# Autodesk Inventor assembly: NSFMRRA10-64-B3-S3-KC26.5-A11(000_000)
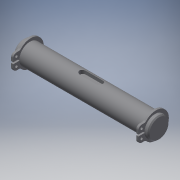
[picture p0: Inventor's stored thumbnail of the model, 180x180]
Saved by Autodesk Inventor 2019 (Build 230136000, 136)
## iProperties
Category: PARTsolutions
Company: MISUMI
Created: 2022-11
Part Number: NSFMRRA10-64-B3-S3-KC26.5-A11(000_000)
Catalog Web Link: www.cadenas.de
Description: NSFMRR, SFMRR, PSFMRR, SSFMRR, NSFHRR, SFHRR, PSFHRR, SSFHRR, NSFRR, SFRR, PSFRR, SSFRR, NSFMRRA, SFMRRA, PSFMRRA, SSFMRRA, NSFHRRA, SFHRRA, PSFHRRA, SSFHRRA, N
Vendor: MISUMI
Document SubType Name: Assembly
Designer: psAdmin
Manufacturer: MISUMI
Mass: 5.06966 g
Surface Area: 26.1875 cm^2
Volume: 5.06966 cm^3
Density: 1 g/cm^3
Title: NSFMRRA10-64-B3-S3-KC26.5-A11
Author: Cadenas PARTsolutions
Comments: Rotary Shafts - Retaining Ring Grooves on Both Ends - Standard
PSOL_IDENT_0: {$CADENAS_DATA/23d-libs/misumi/metric/11_rotary_shafts/psfrra_asmtab.prj},820 {VTYP=3D},{STYP=ASSTAB
PSOL_IDENT_1: },{NB=NSFMRRA10-64-B3-S3-KC26.5-A11(000_000)},{LINA=NSFMRRA10-64-B3-S3-KC26.5-A11},{NN=NSFMRR, SFMRR
PSOL_IDENT_2: , PSFMRR, SSFMRR, NSFHRR, SFHRR, PSFHRR, SSFHRR, NSFRR, SFRR, PSFRR, SSFRR, NSFMRRA, SFMRRA, PSFMRRA
PSOL_IDENT_3: , SSFMRRA, NSFHRRA, SFHRRA, PSFHRRA, SSFHRRA, NSFRRA, SFRRA, PSFRRA, SSFRRA, HFRRA, PHFRRA, PSFRR PS
PSOL_IDENT_4: FRRA, PSFHRR, PSFHRRA, SSFRR, SSFRRA, SSFHRR, SSFHRRA, PPSFRR, PPSFRRA, PPSFHRR, PPSFHRRA, SSSFRR, S
PSOL_IDENT_5: SSFRRA, SSSFHRR, SSSFHRRA_shaft},{DATE=21.04.2022 07:40:19},{GEOMDATE=27.07.2021 08:15:02},{VERSION=
PSOL_IDENT_6: },{LINEID=30},{WBVAR=TS,TYS,MAT,ST,ALT1,L,B,S,ALT2,KC,A,WKC,C,K,E,KZ,Z,ALT3,FC,GALT3,WFC,J,WALT3,V,A
PSOL_IDENT_7: LT4,SFC,SG,AG,ALT5,UC,ALT7,SC,ALT10,KWC,ALT11,WC,ALT32,CD,ALT34,TCJ,WTCJ,XT,HCJ,WHCJ,XH},{WBNUMERIC=
PSOL_IDENT_8: L,B,S,KC,A,WKC,C,K,E,KZ,Z,FC,GALT3,WFC,J,WALT3,V,SFC,SG,AG,UC,SC,KWC,WC,TCJ,WTCJ,XT,HCJ,WHCJ,XH}  {N
PSOL_IDENT_9: B=NSFMRRA10-64-B3-S3-KC26.5-A11(000_000)},{LINA=NSFMRRA10-64-B3-S3-KC26.5-A11},{KT=DUMMY},{PN=NSFMRR
PSOL_IDENT_10: A10-64-B3-S3-KC26.5-A11},{TYPE=NSFMRRA},{TS=SWR},{TYS=H9},{TYSALG= 'H9','h9 (Cold-drawn)','H7','h7 (
PSOL_IDENT_11: Ground)','G6','g6 (Ground)' },{MAT=S45C},{MATALG= 'S45C','S45C Equivalent', 'SUS304','SUS304' },{ST=
PSOL_IDENT_12: },{STALG= '','-','BO','Black Oxide', 'ENP','Electroless Nickel Plating' },{D=10.0},{ALT1=},{ALT1ALG=
PSOL_IDENT_13: '','w/o LKC (Changes L Tolerance)','-LKC','with LKC (Changes L Tolerance)' },{L=64.0},{LALG=[15:800
PSOL_IDENT_14: /0.1]},{LMIN=15},{LMAX=800},{NOTE=25},{B=3.0},{BALG=[3:60/0.1]},{BMAX=60},{S=3.0},{SALG=[3:59/0.1]},
PSOL_IDENT_15: {SMAX=59},{MM=1.15},{DD=9.6},{ARR=STWS10},{ALT2=KC},{ALT2ALG= '', 'w/o Key Grooves','KC','with KC (K
PSOL_IDENT_16: ey Groove)','WKC','with WKC (Two Key Grooves)','KCWKC','with KC + WKC (Three Key Grooves)','KZ','wit
PSOL_IDENT_17: h KC + WKC + KZ (Four Key Grooves)' },{ALT2PN=-KC26.5-A11},{KC=26.5},{KCALG=[0:61/0.1]},{KCMIN=0},{K
PSOL_IDENT_18: CMAX=61},{A=11.0},{AALG=[3:37.5/0.1]},{AMIN=3},{AMAX=37.5},{WKC=0.0},{WKCALG=[0]},{WKCMIN=0},{WKCMAX=
PSOL_IDENT_19: 0},{C=0.0},{CALG=[0]},{CMIN=3},{CMAX=0},{K=0.0},{KALG=[0]},{KMIN=0},{KMAX=59},{E=0.0},{EALG=[0]},{EM
PSOL_IDENT_20: IN=3},{EMAX=62},{KZ=0.0},{KZALG=[0]},{KZMIN=66},{KZMAX=61},{Z=0.0},{ZALG=[0]},{ZMIN=3},{ZMAX=64},{CI
PSOL_IDENT_21: FKC=2},{CIFWKC=1},{CIFK=1},{CIFKZ=2},{PCUT3D=0},{QCUT3D=0},{BB=3},{BBALT2=3},{TT=1.8},{TTALT2=1.8},{
PSOL_IDENT_22: ALT3=},{ALT3ALG= '', 'w/o Set Screw Flat','FC','with FC (Adds a Set Screw Flat)','WFC','with WFC (Ad
PSOL_IDENT_23: ds Two Set Screw Flats)','FCWFC','with FC + WFC (Adds Three Set Screw Flats)' },{ALT3PN=},{FC=0},{FC
PSOL_IDENT_24: ALG=[0]},{FCMIN=0},{FCMAX=63},{GALT3=0},{GALT3ALG=[0]},{GALT3MIN=1},{GALT3MAX=64},{GALT3MAX2=58},{GA
PSOL_IDENT_25: LT3MAX3=61},{WFC=0},{WFCALG=[0]},{WFCMIN=0},{WFCMIN2=2},{WFCMAX=60},{WFCMAX2=-3},{WFCMAX3=-4},{J=0},
PSOL_IDENT_26: {JALG=[0]},{JMIN=1},{JMAX=61},{JMAX2=-2},{JMAX3=-5},{WALT3=0},{WALT3ALG=[0]},{WALT3MIN=0},{WALT3MIN2=
PSOL_IDENT_27: 66},{WALT3MAX=61},{WALT3MAX2=61},{V=0},{VALG=[0]},{VMIN=1},{VMAX=62},{VMAX2=62},{CIFFC=0},{H=0},{ALT
PSOL_IDENT_28: 4=},{ALT4ALG= '', 'w/o SFC (2 Set Screw Flats (Angle Specified))', 'SFC'  , 'with SFC (2 Set Screw F
PSOL_IDENT_29: lats (Angle Specified))'},{ALT4PN=},{SFC=0},{SFCALG=[0]},{SFCMIN=0},{SFCMAX=63},{SG=0},{SGALG=[0]},{
PSOL_IDENT_30: SGMIN=1},{SGMAX=64},{AG=0},{AGALG=[0]},{CIFSFC=0},{ALT5=},{ALT5ALG= '', 'w/o UC (Slit Cam Groove)', '
PSOL_IDENT_31: UC', 'with UC (Slit Cam Groove)'},{ALT5PN=},{UC=0},{UCALG=[0]},{UCMIN=1},{UCMAX=58},{DDALT5=8},{LL1=
PSOL_IDENT_32: 0},{ALT7=},{ALT7ALG= '', 'w/o SC (Wrench Flats)', 'SC', 'with SC (Wrench Flats)'},{ALT7PN=},{SC=0},{
PSOL_IDENT_33: SCALG=[0]},{SCMIN=0},{SCMAX=64},{WALT7=0},{LL2=0},{CIFSC=0},{ALT10=},{ALT10ALG= '','Not applicable'
PSOL_IDENT_34: },{ALT10PN=},{KWC=0},{KWCALG=[0]},{KWCMIN=1},{KWCMAX=0},{WALT10=8},{ALT11=},{ALT11ALG= '','Not appli
PSOL_IDENT_35: cable' },{ALT11PN=},{WC=0.0},{WCALG=[0]},{ALT32=},{ALT32ALG=  '','w/o CD (Changes Part D Chamfering)'
PSOL_IDENT_36: ,'-CD', 'with CD (Changes Part D Chamfering)' },{CD=},{CDALG= '','N/A' },{CD3D=0.5},{CIF32=0},{CIF32
PSOL_IDENT_37: 0=0},{CIF32B=0},{CIF32S=0},{ALT32PN=},{ERRORPN=},{ERRORRALT2=OK},{ERRORRALT3=OK},{ERRORRALT4=NG},{ER
PSOL_IDENT_38: RORRALT5=NG},{ERRORRALT7=NG},{ERRORRALT10=OK},{ERRORALT23=OK},{ERRORALT24=OK},{ERRORALT25=OK},{ERROR
PSOL_IDENT_39: ALT27=OK},{ERRORALT210=OK},{ERRORALT34=OK},{ERRORALT35=OK},{ERRORALT37=OK},{ERRORALT310=OK},{ERRORAL
PSOL_IDENT_40: T45=OK},{ERRORALT47=OK},{ERRORALT410=OK},{ERRORALT75=OK},{ERRORALT510=OK},{ERRORALT710=OK},{ALT34=},
PSOL_IDENT_41: {ALT34ALG= '','Not applicable'},{TCJ=0},{WTCJ=0},{XT=0},{TM=4},{TCJALG=[0]},{TCJMIN=7.000},{TCJMAX=2
PSOL_IDENT_42: 9.000},{TCJMAX1=29.000},{HCJ=0},{WHCJ=0},{XH=0},{HP=4},{HCJALG=[0]},{HCJMIN=7.000},{HCJMAX=29.000},{
PSOL_IDENT_43: HCJMAX1=29.000},{LCJ=0},{LMINX=15},{XALG=[0]},{XCJMIN=7},{PPATH=11_components/psfrra/psfrra_asmtpl.p
PSOL_IDENT_44: rj},{WHCJALG=[0]},{WTCJALG=[0]},{XHALG=[0]}
NB: NSFMRRA10-64-B3-S3-KC26.5-A11(000_000)
NN: NSFMRR, SFMRR, PSFMRR, SSFMRR, NSFHRR, SFHRR, PSFHRR, SSFHRR, NSFRR, SFRR, PSFRR, SSFRR, NSFMRRA, SFMRRA, PSFMRRA, SSFMRRA, NSFHRRA, SFHRRA, PSFHRRA, SSFHRRA, N
NT: Rotary Shafts - Retaining Ring Grooves on Both Ends - Standard
NBSYN: $PN.($ALT34.$TCJ.$WTCJ.$XT._$HCJ.$WHCJ.$XH.)
LINA: NSFMRRA10-64-B3-S3-KC26.5-A11
CATALOG: Misumi
PN: NSFMRRA10-64-B3-S3-KC26.5-A11
TS: With Retaining Ring
TYS: h9 (Cold-drawn)
MAT: S45C Equivalent
ST: -
D: 10
ALT1: w/o LKC (Changes L Tolerance)
L: 64
B: 3
S: 3
MM: 1.15
DD: 9.6
ALT2: with KC (Key Groove)
KC: 26.5
A: 11
WKC: 0
C: 0
K: 0
E: 0
KZ: 0
Z: 0
ALT3: w/o Set Screw Flat
FC: 0
GALT3: 0
WFC: 0
J: 0
WALT3: 0
V: 0
ALT4: w/o SFC (2 Set Screw Flats (Angle Specified))
SFC: 0
SG: 0
AG: 0
ALT5: w/o UC (Slit Cam Groove)
UC: 0
ALT7: w/o SC (Wrench Flats)
SC: 0
ALT10: Not applicable
KWC: 0
ALT11: Not applicable
WC: 0
ALT32: w/o CD (Changes Part D Chamfering)
CD: N/A
ALT34: Not applicable
TCJ: 0
WTCJ: 0
XT: 0
HCJ: 0
WHCJ: 0
XH: 0
SUPPLIER: MISUMI
ARTICLENO: NSFMRRA10-64-B3-S3-KC26.5-A11(000_000)
BOMINFO: NSFMRRA10-64-B3-S3-KC26.5-A11
CREATOR: CADENAS GmbH
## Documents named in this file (3)
- e:\temp\worker_COMMON_7\temp\tmp_276_134_zwONR\format_0\NSFMRRA10-64-B3-S3-KC26_5-A11(000_000).iam
- e:\temp\worker_COMMON_7\temp\tmp_276_134_zwONR\format_0\NSFMRRA10-64-B3-S3-KC26_5-A11(000_000)_s.ipt
- e:\temp\worker_COMMON_7\temp\tmp_276_134_zwONR\format_0\STWN10.ipt
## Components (3 placed, 2 different names)
1. NSFMRRA10-64-B3-S3-KC26_5-A11(000_000)_s:1 — to_ring_b_XY@1 <-> 1_XY@2, to_ring_b_Z@1 <-> 1_Z@2, to_ring_b_YZ@1 <-> 1_YZ@2, to_ring_s_XY@1 <-> 1_XY@3, to_ring_s_Z@1 <-> 1_Z@3, to_ring_s_YZ@1 <-> 1_YZ@3
2. STWN10:1 — to_ring_b_XY@1 <-> 1_XY@2, to_ring_b_Z@1 <-> 1_Z@2, to_ring_b_YZ@1 <-> 1_YZ@2
3. STWN10:2 — to_ring_s_XY@1 <-> 1_XY@3, to_ring_s_Z@1 <-> 1_Z@3, to_ring_s_YZ@1 <-> 1_YZ@3
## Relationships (6: Mate 3, Angle 2, Flush 1)
- to_ring_b_XY@1 <-> 1_XY@2 [Mate]: NSFMRRA10-64-B3-S3-KC26_5-A11(000_000)_s:1 ↔ STWN10:1
- to_ring_b_Z@1 <-> 1_Z@2 [Mate]: NSFMRRA10-64-B3-S3-KC26_5-A11(000_000)_s:1 ↔ STWN10:1
- to_ring_b_YZ@1 <-> 1_YZ@2 [Angle]: NSFMRRA10-64-B3-S3-KC26_5-A11(000_000)_s:1 ↔ STWN10:1
- to_ring_s_XY@1 <-> 1_XY@3 [Flush]: NSFMRRA10-64-B3-S3-KC26_5-A11(000_000)_s:1 ↔ STWN10:2
- to_ring_s_Z@1 <-> 1_Z@3 [Mate]: NSFMRRA10-64-B3-S3-KC26_5-A11(000_000)_s:1 ↔ STWN10:2
- to_ring_s_YZ@1 <-> 1_YZ@3 [Angle]: NSFMRRA10-64-B3-S3-KC26_5-A11(000_000)_s:1 ↔ STWN10:2
